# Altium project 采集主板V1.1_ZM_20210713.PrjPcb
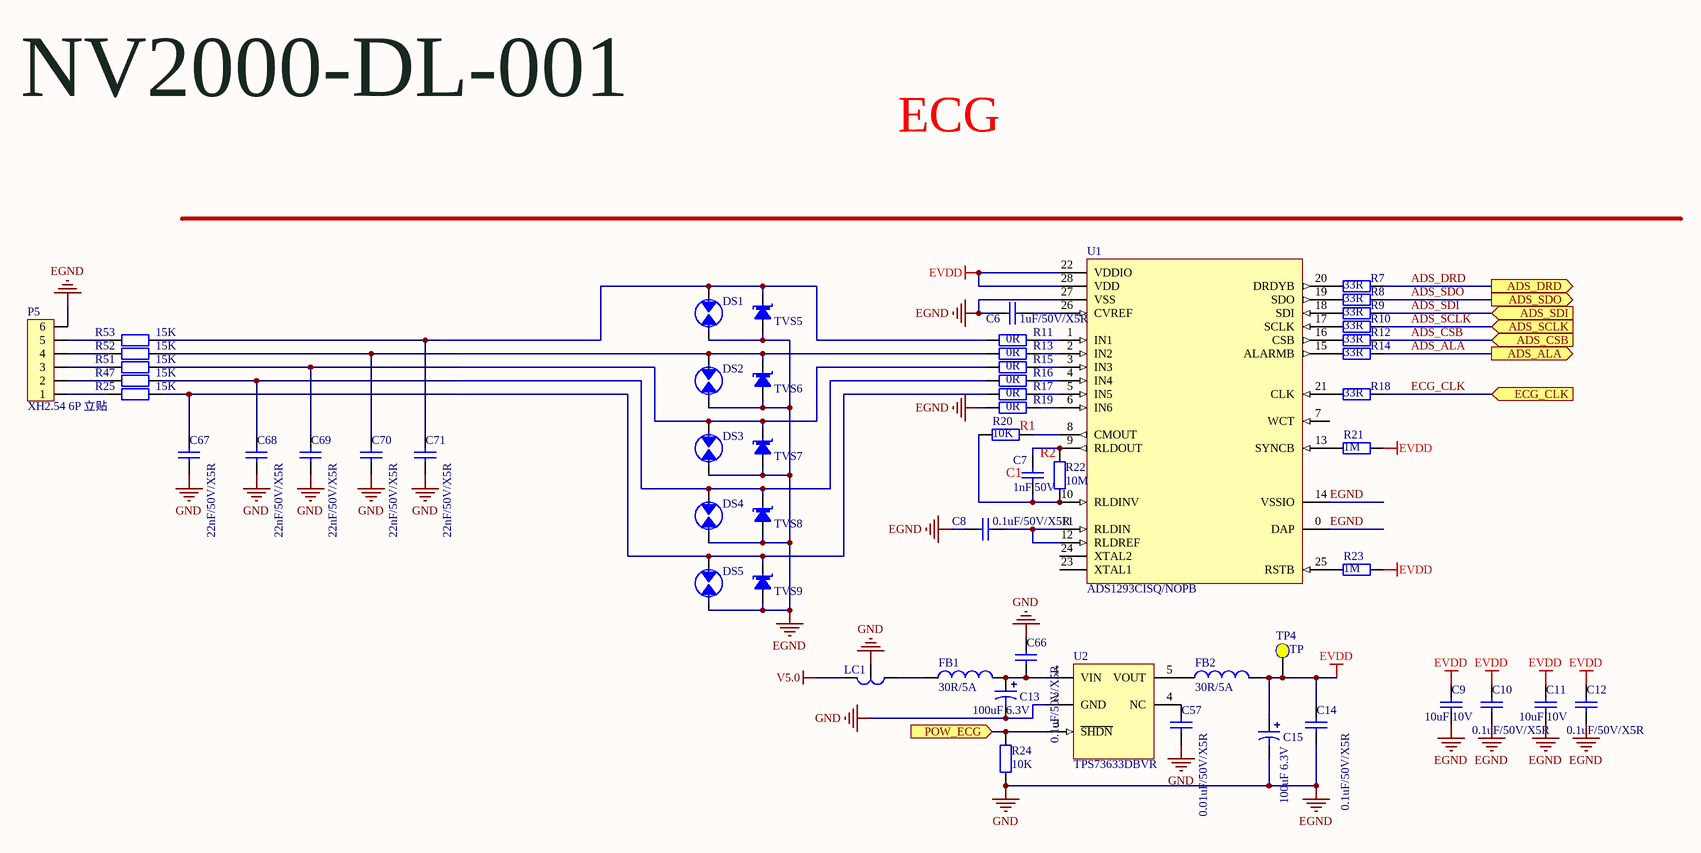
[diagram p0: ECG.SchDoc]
4 sheets, 191 parts. Net scope: flat (ports and power ports of the same name join across sheets).
Board file: 采集主板V1.1_ZM_20210713.PcbDoc
Sheets:
  ECG.SchDoc
  POWER.SchDoc
  PRESS.SchDoc
  控制部分.SchDoc

## Sheet ECG.SchDoc
size A3

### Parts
C6  1uF/50V/X5R  [SMD-0603C]
C7  1nF 50V  [SMD-0603C]
C8  0.1uF/50V/X5R  [SMD-0603C]
C9  10uF 10V  [SMD-0603C]
C10  0.1uF/50V/X5R  [SMD-0603C]
C11  10uF 10V  [SMD-0603C]
C12  0.1uF/50V/X5R  [SMD-0603C]
C13  100uF 6.3V  [SMD-3528-B]
C14  0.1uF/50V/X5R  [SMD-0603C]
C15  100uF 6.3V  [SMD-3528-B]
C57  0.01uF/50V/X5R  [SMD-0603C]
C66  0.1uF/50V/X5R  [SMD-0603C]
C67  22nF/50V/X5R  [SMD-0603C]
C68  22nF/50V/X5R  [SMD-0603C]
C69  22nF/50V/X5R  [SMD-0603C]
C70  22nF/50V/X5R  [SMD-0603C]
C71  22nF/50V/X5R  [SMD-0603C]
DS1  UN1812-90CSMD  [SMD-1812]  (value not drawn)
DS2  UN1812-90CSMD  [SMD-1812]  (value not drawn)
DS3  UN1812-90CSMD  [SMD-1812]  (value not drawn)
DS4  UN1812-90CSMD  [SMD-1812]  (value not drawn)
DS5  UN1812-90CSMD  [SMD-1812]  (value not drawn)
FB1  30R/5A  [0603r]
FB2  30R/5A  [0603r]
LC1  NFM18PC104R1C3  [NFM21P-0805]  (value not drawn)
P5  XH2.54 6P 立贴  [XH-2.54-6P-LI]
R7  33R  [SMD-0603]
R8  33R  [SMD-0603]
R9  33R  [SMD-0603]
R10  33R  [SMD-0603]
R11  0R  [SMD-0805]
R12  33R  [SMD-0603]
R13  0R  [SMD-0805]
R14  33R  [SMD-0603]
R15  0R  [SMD-0805]
R16  0R  [SMD-0805]
R17  0R  [SMD-0805]
R18  33R  [SMD-0603]
R19  0R  [SMD-0805]
R20  10K  [SMD-0603]
R21  1M  [SMD-0603]
R22  10M  [SMD-0603]
R23  1M  [SMD-0603]
R24  10K  [SMD-0603]
R25  15K  [SMD-0603]
R47  15K  [SMD-0603]
R51  15K  [SMD-0603]
R52  15K  [SMD-0603]
R53  15K  [SMD-0603]
TP4  TP  [TP]
TVS5  TVS-S  [SOD-323]  (value not drawn)
TVS6  TVS-S  [SOD-323]  (value not drawn)
TVS7  TVS-S  [SOD-323]  (value not drawn)
TVS8  TVS-S  [SOD-323]  (value not drawn)
TVS9  TVS-S  [SOD-323]  (value not drawn)
U1  ADS1293CISQ/NOPB  [QFN-28]
U2  TPS73633DBVR  [SOT23-5]

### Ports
ADS_ALA (out), ADS_CSB (in), ADS_DRD (out), ADS_SCLK (in), ADS_SDI (in), ADS_SDO (out), ECG_CLK (in), POW_ECG (in)

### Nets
EGND: C6.1 C8.1 C9.1 C10.1 C11.1 C12.1 C13.2 C14.1 C15.2 C57.1 C66.2 C67.1 C68.1 C69.1 C70.1 C71.1 DS1.2 DS2.2 DS3.2 DS4.2 DS5.2 LC1.2 P5.6 R19.1 R24.2 TVS5.1(A) TVS6.1(A) TVS7.1(A) TVS8.1(A) TVS9.1(A) U1.0(DAP) U1.14(VSSIO) U1.27(VSS) U2.2(GND)  [also labelled GND]
EVDD: C9.2 C10.2 C11.2 C12.2 C14.2 C15.1 FB2.2 R21.1 R23.1 TP4.1(TP) U1.22(VDDIO) U1.28(VDD)
V5.0: LC1.3
ADS_ALA: R14.1 ; port ADS_ALA
ADS_CSB: R12.1 ; port ADS_CSB
ADS_DRD: R7.1 ; port ADS_DRD
ADS_SCLK: R10.1 ; port ADS_SCLK
ADS_SDI: R9.1 ; port ADS_SDI
ADS_SDO: R8.1 ; port ADS_SDO
ECG_CLK: R18.1 ; port ECG_CLK
NetC6_2: C6.2 U1.26(CVREF)
NetC7_1: C7.1 R22.1 U1.9(RLDOUT)
NetC7_2: C7.2 R20.2 R22.2 U1.10(RLDINV)
NetC8_2: C8.2 U1.11(RLDIN) U1.12(RLDREF)
NetC13_1: C13.1 C66.1 FB1.2 U2.1(VIN)
NetC57_2: C57.2 U2.4(NC)
NetC67_2: C67.2 DS5.1 R17.1 R25.2 TVS9.2(B)
NetC68_2: C68.2 DS4.1 R16.1 R47.2 TVS8.2(B)
NetC69_2: C69.2 DS3.1 R15.1 R51.2 TVS7.2(B)
NetC70_2: C70.2 DS2.1 R13.1 R52.2 TVS6.2(B)
NetC71_2: C71.2 DS1.1 R11.1 R53.2 TVS5.2(B)
NetFB1_1: FB1.1 LC1.1
NetFB2_1: FB2.1 U2.5(VOUT)
NetP5_1: P5.1 R25.1
NetP5_2: P5.2 R47.1
NetP5_3: P5.3 R51.1
NetP5_4: P5.4 R52.1
NetP5_5: P5.5 R53.1
NetR7_2: R7.2 U1.20(DRDYB)
NetR8_2: R8.2 U1.19(SDO)
NetR9_2: R9.2 U1.18(SDI)
NetR10_2: R10.2 U1.17(SCLK)
NetR11_2: R11.2 U1.1(IN1)
NetR12_2: R12.2 U1.16(CSB)
NetR13_2: R13.2 U1.2(IN2)
NetR14_2: R14.2 U1.15(ALARMB)
NetR15_2: R15.2 U1.3(IN3)
NetR16_2: R16.2 U1.4(IN4)
NetR17_2: R17.2 U1.5(IN5)
NetR18_2: R18.2 U1.21(CLK)
NetR19_2: R19.2 U1.6(IN6)
NetR20_1: R20.1 U1.8(CMOUT)
NetR21_2: R21.2 U1.13(SYNCB)
NetR23_2: R23.2 U1.25(RSTB)
NetR24_1: R24.1 U2.3(~{SHDN}) ; port POW_ECG

Not connected (* = marked no-connect by the designer): U1 7(WCT) 23(XTAL1) 24(XTAL2)

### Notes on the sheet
- NV2000-DL-001
- ECG
- (near R20) R1
- R2
- (near C7) C1

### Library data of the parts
C6 C8 C10 C12 C14 C57 C66-C71 = CAP4: 贴片电容 10%
C7 = CAP4: 贴片电容 5%
C9 C11 = CAP4: 贴片电容 20%
C13 C15 = CAP2: 钽电容
DS1-DS5 = DISCHARE-1: 气体放电管 90V
FB1 FB2 = Inductor: Code_IEC: 1005; Value: 10mH
LC1 = SMD-EMIFIL-0603: LC滤波器
P5 = SIP-6: 心电接口
R7-R19 R21 R23 = RES0: 贴片电阻 5%
R20 R22 R24 R25 R47 R51-R53 = RES0: 贴片电阻 1%
TP4 = TP_POINT
TVS5-TVS9 = TVS-S: 单向TVS
U1 = ADS1293: ECG AFE
U2 = MCP1802: LDO

## Sheet POWER.SchDoc
size A4
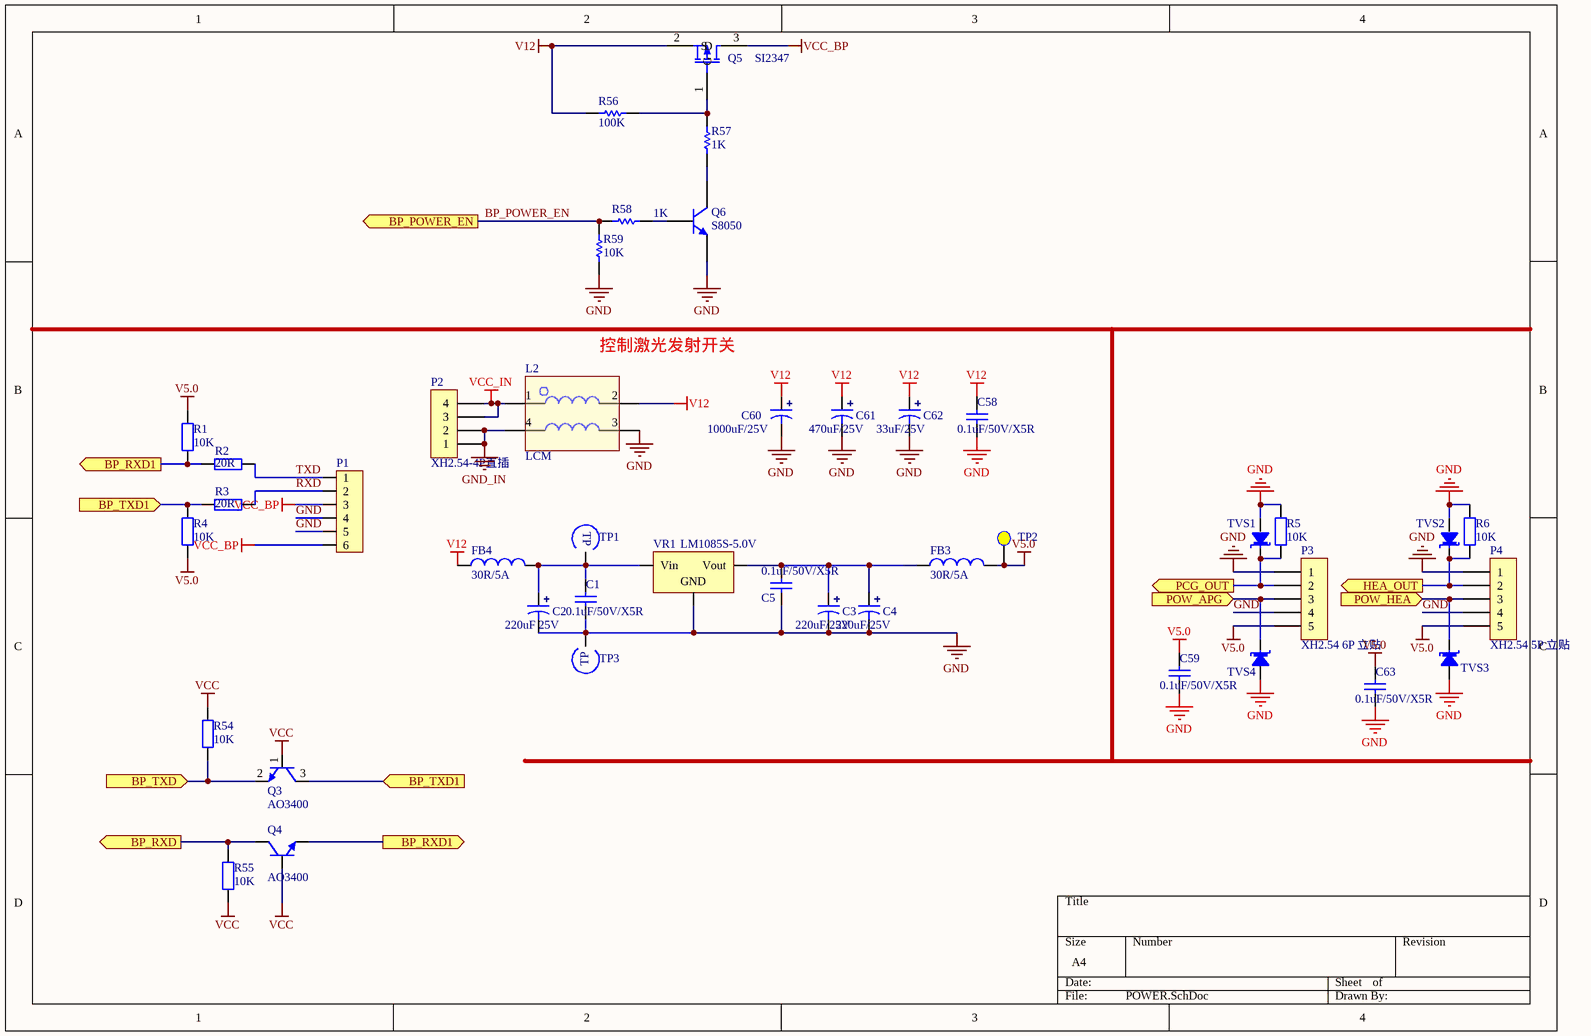
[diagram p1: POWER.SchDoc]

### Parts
C1  0.1uF/50V/X5R  [SMD-0603C]
C2  220uF 25V  [SMD-6.3*7.7]
C3  220uF/25V  [SMD-6.3*7.7]
C4  220uF/25V  [SMD-6.3*7.7]
C5  0.1uF/50V/X5R  [SMD-0603C]
C58  0.1uF/50V/X5R  [SMD-0603C]
C59  0.1uF/50V/X5R  [SMD-0603C]
C60  1000uF/25V  [10*16]
C61  470uF/25V  [8*12]
C62  33uF/25V  [5*7]
C63  0.1uF/50V/X5R  [SMD-0603C]
FB3  30R/5A  [0603r]
FB4  30R/5A  [0603r]
L2  LCM  [LCM]
P1  XH2.54 6P 立贴  [XH-2.54-6P-LI]  (value not drawn)
P2  XH2.54-4P直插  [4X2.54MMZ]
P3  XH2.54 6P 立贴  [XH-2.54-5P-LI]
P4  XH2.54 5P 立贴  [XH-2.54-5P-LI]
Q3  AO3400  [SOT-23]
Q4  AO3400  [SOT-23]
Q5  SI2347  [SOT23-3]
Q6  S8050  [SOT23-3]
R1  10K  [SMD-0603]
R2  20R  [SMD-0603]
R3  20R  [SMD-0603]
R4  10K  [SMD-0603]
R5  10K  [SMD-0603]
R6  10K  [SMD-0603]
R54  10K  [SMD-0603]
R55  10K  [SMD-0603]
R56  100K  [0603R]
R57  1K  [0603R]
R58  1K  [0603R]
R59  10K  [0603R]
TP1  TP  [TP]  (value not drawn)
TP2  TP  [TP]  (value not drawn)
TP3  TP  [TP]  (value not drawn)
TVS1  TVS-S  [SOD-323]  (value not drawn)
TVS2  TVS-S  [SOD-323]  (value not drawn)
TVS3  TVS-S  [SOD-323]  (value not drawn)
TVS4  TVS-S  [SOD-323]  (value not drawn)
VR1  LM1085S-5.0V  [TO-263-3]

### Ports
BP_POWER_EN (out), BP_RXD1 (out), BP_RXD (out), BP_TXD1 (in), BP_TXD (in), HEA_OUT (out), PCG_OUT (out), POW_APG (in), POW_HEA (in)

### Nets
GND: C1.1 C2.2 C3.2 C4.2 C5.1 C58.1 C59.1 C60.2 C61.2 C62.2 C63.1 L2.3 P1.4 P1.5 P3.1 P3.4 P4.1 P4.4 Q6.2(E) R5.1 R6.1 R59.2 TP3.1 TVS1.1(A) TVS2.1(A) TVS3.1(A) TVS4.1(A) VR1.1(GND)  [project net EGND]
GND_IN: L2.4 P2.1 P2.2
V5.0: C59.2 C63.2 FB3.2 P3.5 P4.5 R1.1 R4.2 TP2.1(TP)
V12: C58.2 C60.1 C61.1 C62.1 FB4.1 L2.2 Q5.2(S) R56.2
VCC: Q3.1(B) Q4.1(B) R54.2 R55.1
VCC_BP: P1.3 P1.6 Q5.3(D)
VCC_IN: L2.1 P2.3 P2.4
BP_POWER_EN: R58.2 R59.1 ; port BP_POWER_EN
RXD: P1.2 R3.1
TXD: P1.1 R2.1
NetC1_2: C1.2 C2.1 FB4.2 TP1.1 VR1.3(Vin)
NetC3_1: C3.1 C4.1 C5.2 FB3.1 VR1.2(Vout)
NetP3_2: P3.2 R5.2 TVS1.2(B) ; port PCG_OUT
NetP3_3: P3.3 TVS4.2(B) ; port POW_APG
NetP4_2: P4.2 R6.2 TVS2.2(B) ; port HEA_OUT
NetP4_3: P4.3 TVS3.2(B) ; port POW_HEA
NetQ3_2: Q3.2(E) R54.1 ; port BP_TXD
NetQ3_3: Q3.3(C) R3.2 R4.1 ; port BP_TXD1
NetQ4_2: Q4.2(E) R1.2 R2.2 ; port BP_RXD1
NetQ4_3: Q4.3(C) R55.2 ; port BP_RXD
NetQ5_1: Q5.1(G) R56.1 R57.2
NetQ6_1: Q6.1(B) R58.1
NetQ6_3: Q6.3(C) R57.1

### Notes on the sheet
- (near L2) 控制激光发射开关

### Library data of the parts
C1 C5 C58 C59 C63 = CAP4: 贴片电容 20%
C2-C4 C60-C62 = CAP2: 电解电容
FB3 FB4 = Inductor: Code_IEC: 1005; Value: 10mH
P1 = SIP-6: 血压计接口
P2 = SIP-4
P3 = SIP-5: 颈动脉传感器接口
P4 = SIP-5: 心音传感器接口
Q3 Q4 = NPN-1: NPN
Q5 = MOSFET-P: P-Channel MOSFET
Q6 = NPN: NPN Bipolar Transistor
R1-R6 R54 R55 = R: 贴片电阻 1%
R56-R59 = Res1: Resistor
TP1 TP3 = TP-1: 测试点
TP2 = TP_POINT: 测试点
TVS1-TVS4 = TVS-S: 单向TVS
VR1 = LM1117: 三端稳压器

## Sheet PRESS.SchDoc
size A4
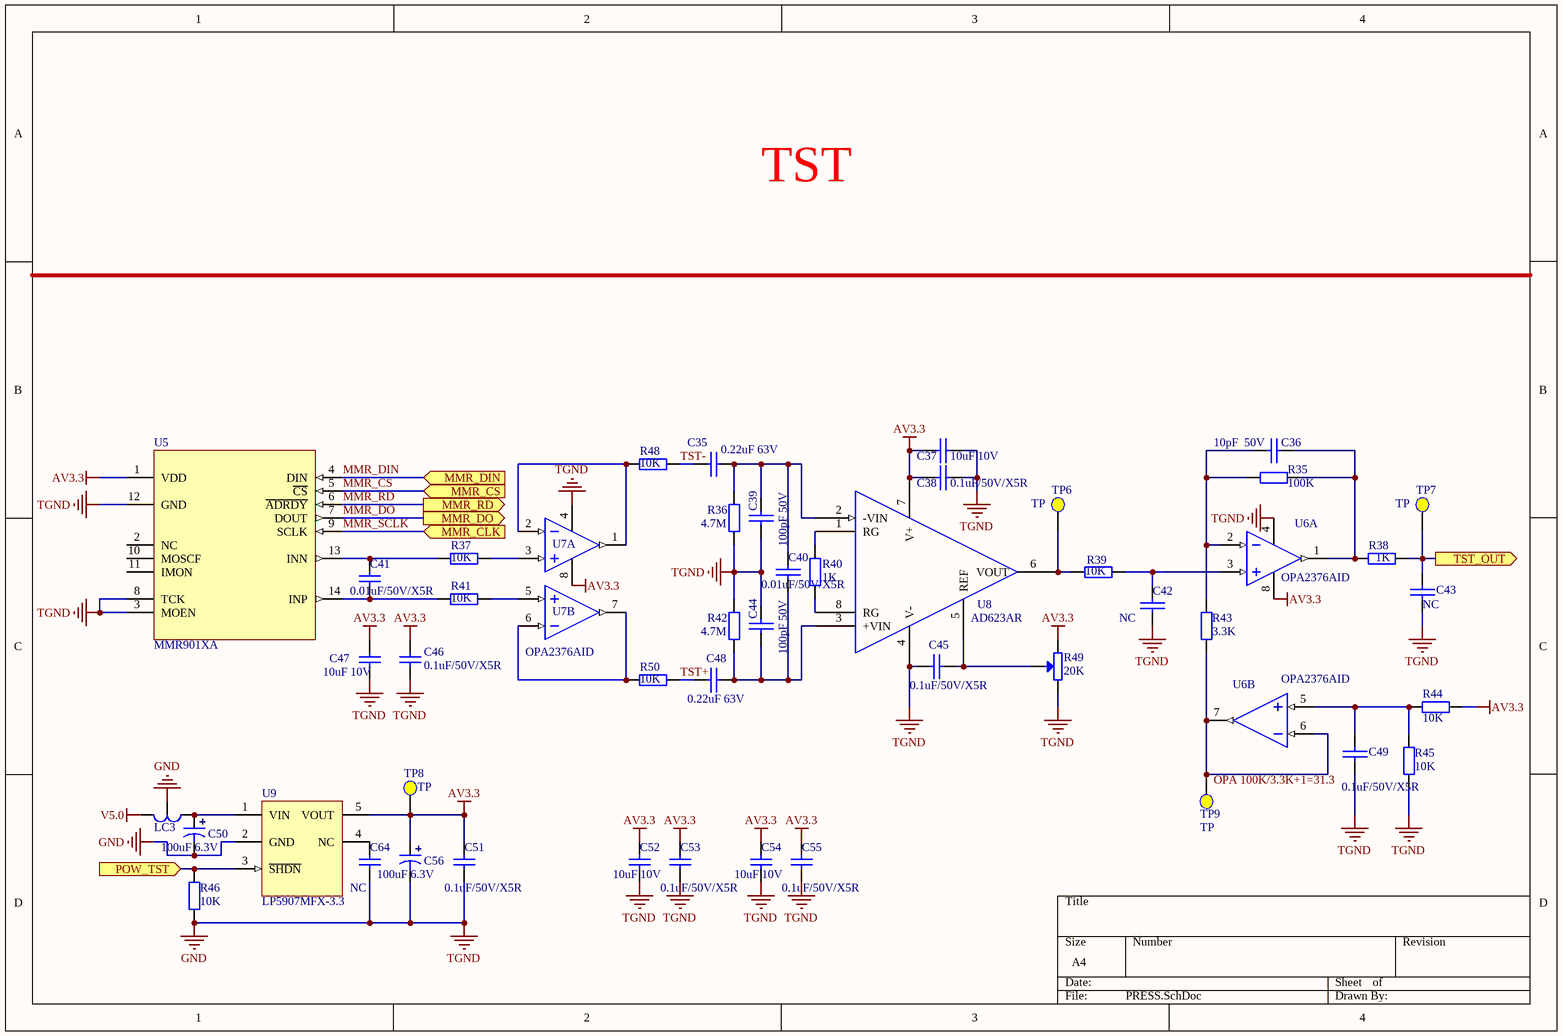
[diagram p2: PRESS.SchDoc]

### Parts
C35  0.22uF 63V  [CAP-7.5*5.08]
C36  10pF  50V  [SMD-0603C]
C37  10uF 10V  [SMD-0603C]
C38  0.1uF/50V/X5R  [SMD-0603C]
C39  100pF 50V  [SMD-0603C]
C40  0.01uF/50V/X5R  [SMD-0603C]
C41  0.01uF/50V/X5R  [SMD-0603C]
C42  NC  [SMD-0603C]
C43  NC  [SMD-0603C]
C44  100pF 50V  [SMD-0603C]
C45  0.1uF/50V/X5R  [SMD-0603C]
C46  0.1uF/50V/X5R  [SMD-0603C]
C47  10uF 10V  [SMD-0603C]
C48  0.22uF 63V  [CAP-7.5*5.08]
C49  0.1uF/50V/X5R  [SMD-0603C]
C50  100uF 6.3V  [SMD-3528-B]
C51  0.1uF/50V/X5R  [SMD-0603C]
C52  10uF 10V  [SMD-0603C]
C53  0.1uF/50V/X5R  [SMD-0603C]
C54  10uF 10V  [SMD-0603C]
C55  0.1uF/50V/X5R  [SMD-0603C]
C56  100uF 6.3V  [SMD-3528-B]
C64  NC  [SMD-0603C]
LC3  NFM18PC104R1C3  [NFM21P-0805]  (value not drawn)
R35  100K  [SMD-0603]
R36  4.7M  [SMD-0603]
R37  10K  [SMD-0603]
R38  1K  [SMD-0603]
R39  10K  [SMD-0603]
R40  1K  [SMD-0603]
R41  10K  [SMD-0603]
R42  4.7M  [SMD-0603]
R43  3.3K  [SMD-0603]
R44  10K  [SMD-0603]
R45  10K  [SMD-0603]
R46  10K  [SMD-0603]
R48  10K  [SMD-0603]
R49  20K  [VR-05]
R50  10K  [SMD-0603]
TP6  TP  [TP]
TP7  TP  [TP]
TP8  TP  [TP]
TP9  TP  [TP]
U5  MMR901XA  [MMR901XA]
U6  OPA2376AID  [SOIC-8]  (parts A,B of 2)
U7  OPA2376AID  [SOIC-8]  (parts A,B of 2)
U8  AD623AR  [SOIC-8]
U9  LP5907MFX-3.3  [SOT23-5]

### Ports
MMR_CLK (in), MMR_CS (in), MMR_DIN (in), MMR_DO (out), MMR_RD (out), POW_TST (in), TST_OUT (out)

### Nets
AV3.3: C37.2 C38.2 C46.2 C47.2 C51.2 C52.2 C53.2 C54.2 C55.2 C56.1 R44.1 R49.3 TP8.1(TP) U5.1(VDD) U6.8(V+) U7.8(V+) U8.7(V+) U9.5(VOUT)
GND: C37.1 C38.1 C39.2 C42.1 C43.2 C44.1 C45.1 C46.1 C47.1 C49.1 C50.2 C51.1 C52.1 C53.1 C54.1 C55.1 C56.2 C64.1 LC3.2 R36.2 R42.1 R45.1 R46.2 R49.1 U5.3(MOEN) U5.8(TCK) U5.12(GND) U6.4(V-) U7.4(V-) U8.4(V-) U9.2(GND)  [also labelled TGND]  [project net EGND]
V5.0: LC3.3
MMR_CS: U5.5(~{CS}) ; port MMR_CS
MMR_DIN: U5.4(DIN) ; port MMR_DIN
MMR_DO: U5.7(DOUT) ; port MMR_DO
MMR_RD: U5.6(~{ADRDY}) ; port MMR_RD
MMR_SCLK: U5.9(SCLK) ; port MMR_CLK
TST+: C48.2 R50.1
TST-: C35.1 R48.1
NetC35_2: C35.2 C39.1 C40.1 R36.1 U8.2(-VIN)
NetC36_1: C36.1 R35.1 R43.2 U6.2(IN1-)
NetC36_2: C36.2 R35.2 R38.1 U6.1(OUT1)
NetC40_2: C40.2 C44.2 C48.1 R42.2 U8.3(+VIN)
NetC41_1: C41.1 R41.2 U5.14(INP)
NetC41_2: C41.2 R37.2 U5.13(INN)
NetC42_2: C42.2 R39.2 U6.3(IN1+)
NetC43_1: C43.1 R38.2 TP7.1(TP) ; port TST_OUT
NetC45_2: C45.2 R49.2 U8.5(REF)
NetC49_2: C49.2 R44.2 R45.2 U6.5(IN2+)
NetC50_1: C50.1 LC3.1 U9.1(VIN)
NetC64_2: C64.2 U9.4(NC)
NetR37_1: R37.1 U7.3(IN1+)
NetR39_1: R39.1 TP6.1(TP) U8.6(VOUT)
NetR40_1: R40.1 U8.1(RG)
NetR40_2: R40.2 U8.8(RG)
NetR41_1: R41.1 U7.5(IN2+)
NetR43_1: R43.1 TP9.1(TP) U6.6(IN2-) U6.7(OUT2)
NetR46_1: R46.1 U9.3(~{SHDN}) ; port POW_TST
NetR48_2: R48.2 U7.1(OUT1) U7.2(IN1-)
NetR50_2: R50.2 U7.6(IN2-) U7.7(OUT2)

Not connected (* = marked no-connect by the designer): U5 2(NC) 10(MOSCF) 11(IMON)

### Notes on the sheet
- TST
- OPA 100K/3.3K+1=31.3

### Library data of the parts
C35 C48 = CAP: CBB电容
C36 C38-C40 C42-C45 C49 = CAP: 贴片电容 5%
C37 = CAP: 贴片电容 20%
C41 C46 C51 C53 C55 C64 = CAP4: 贴片电容 10%
C47 C52 C54 = CAP4: 贴片电容 20%
C50 C56 = CAP2: 钽电容
LC3 = SMD-EMIFIL-0603: LC滤波器
R35-R43 R46 R48 R50 = RES0: 贴片电阻 1%
R44 R45 = RES0: 贴片电阻 1% 低温票电阻
R49 = RES4: 可调电阻
TP6-TP9 = TP_POINT
U5 = MMR901: 压力传感器
U6 = LM358: 运放
U7 = LM358: 高精度运放
U8 = Component_1: 仪表运放; Part Field 1: 0
U9 = MCP1802: LDO

## Sheet 控制部分.SchDoc
size A4
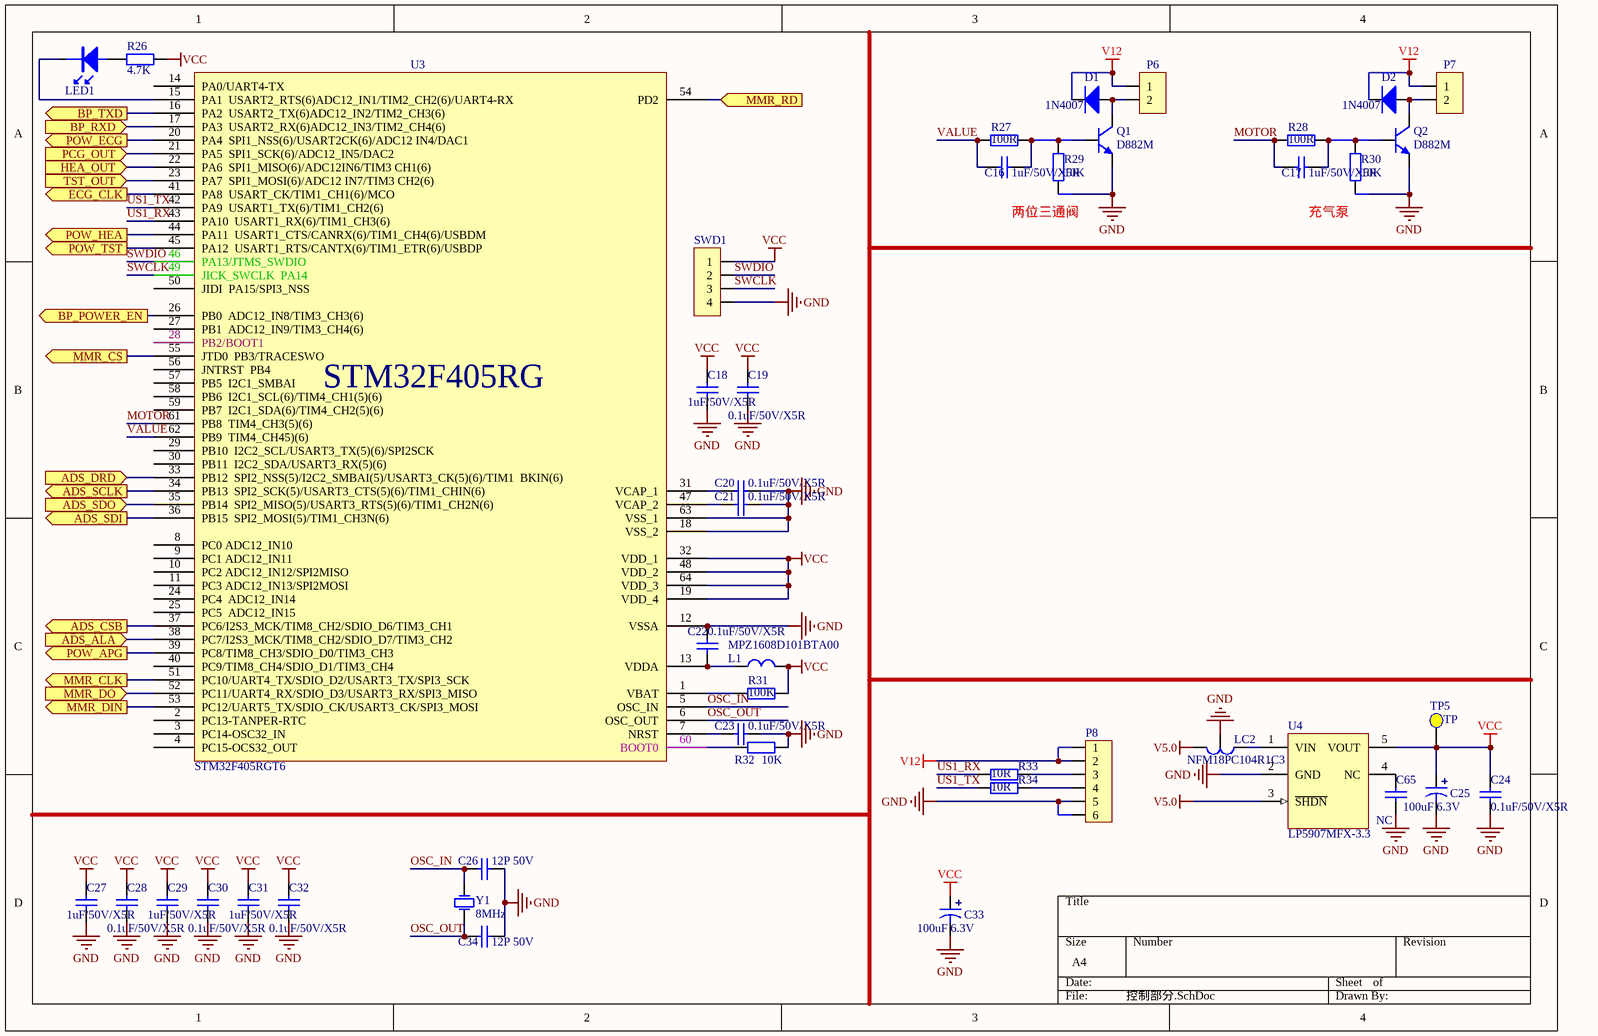
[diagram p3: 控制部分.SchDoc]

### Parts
C16  1uF/50V/X5R  [SMD-0603C]
C17  1uF/50V/X5R  [SMD-0603C]
C18  1uF/50V/X5R  [SMD-0603C]
C19  0.1uF/50V/X5R  [SMD-0603C]
C20  0.1uF/50V/X5R  [SMD-0603C]
C21  0.1uF/50V/X5R  [SMD-0603C]
C22  0.1uF/50V/X5R  [SMD-0603C]
C23  0.1uF/50V/X5R  [SMD-0603C]
C24  0.1uF/50V/X5R  [SMD-0603C]
C25  100uF 6.3V  [SMD-3528-B]
C26  12P 50V  [SMD-0603C]
C27  1uF/50V/X5R  [SMD-0603C]
C28  0.1uF/50V/X5R  [SMD-0603C]
C29  1uF/50V/X5R  [SMD-0603C]
C30  0.1uF/50V/X5R  [SMD-0603C]
C31  1uF/50V/X5R  [SMD-0603C]
C32  0.1uF/50V/X5R  [SMD-0603C]
C33  100uF 6.3V  [SMD-3528-B]
C34  12P 50V  [SMD-0603C]
C65  NC  [SMD-0603C]
D1  1N4007  [DO-214-AC]
D2  1N4007  [DO-214-AC]
L1  MPZ1608D101BTA00  [SMD-0603]
LC2  NFM18PC104R1C3  [NFM18P-0603]
LED1  蓝  [SMD-0603D]  (value not drawn)
P6  VH2.54-2P  [XH-2.54-2P-LI]  (value not drawn)
P7  VH2.54-2P  [XH-2.54-2P-LI]  (value not drawn)
P8  XH2.54 6P 立贴  [XH-2.54-6P-LI]  (value not drawn)
Q1  D882M  [SOT-89-3]
Q2  D882M  [SOT-89-3]
R26  4.7K  [SMD-0603]
R27  100R  [SMD-0603]
R28  100R  [SMD-0603]
R29  10K  [SMD-0603]
R30  10K  [SMD-0603]
R31  100K  [SMD-0603]
R32  10K  [SMD-0603]
R33  10R  [SMD-0603]
R34  10R  [SMD-0603]
SWD1  SIP-4  [SIP-4]  (value not drawn)
TP5  TP  [TP]
U3  STM32F405RGT6  [LQFP64_N]
U4  LP5907MFX-3.3  [SOT23-5]
Y1  8MHz  [XTAL-3225-2]

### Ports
ADS_ALA (in), ADS_CSB (out), ADS_DRD (in), ADS_SCLK (out), ADS_SDI (out), ADS_SDO (in), BP_POWER_EN (out), BP_RXD (in), BP_TXD (out), ECG_CLK (out), HEA_OUT (in), MMR_CLK (out), MMR_CS (out), MMR_DIN (out), MMR_DO (in), MMR_RD (in), PCG_OUT (in), POW_APG (out), POW_ECG (out), POW_HEA (out), POW_TST (out), TST_OUT (in)

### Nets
GND: C18.1 C19.1 C20.1 C21.1 C22.1 C23.2 C24.1 C25.2 C26.1 C27.1 C28.1 C29.1 C30.1 C31.1 C32.1 C33.2 C34.1 C65.1 LC2.2 P8.5 P8.6 Q1.3(E) Q2.3(E) R29.2 R30.2 R32.2 SWD1.4 U3.12(VSSA) U3.18(VSS_2) U3.63(VSS_1) U4.2(GND)  [project net EGND]
V5.0: LC2.3 U4.3(~{SHDN})
V12: D1.2(K) D2.2(K) P6.1 P7.1 P8.1 P8.2
VCC: C18.2 C19.2 C24.2 C25.1 C27.2 C28.2 C29.2 C30.2 C31.2 C32.2 C33.1 L1.2 R26.1 R31.1 SWD1.1 TP5.1(TP) U3.19(VDD_4) U3.32(VDD_1) U3.48(VDD_2) U3.64(VDD_3) U4.5(VOUT)
ADS_ALA: U3.38(PC7/I2S3_MCK/TIM8_CH2/SDIO_D7/TIM3_CH2) ; port ADS_ALA
ADS_CSB: U3.37(PC6/I2S3_MCK/TIM8_CH2/SDIO_D6/TIM3_CH1) ; port ADS_CSB
ADS_DRD: U3.33(PB12__SPI2_NSS(5)/I2C2_SMBAI(5)/USART3_CK(5)(6)/TIM1__BKIN(6)) ; port ADS_DRD
ADS_SCLK: U3.34(PB13__SPI2_SCK(5)/USART3_CTS(5)(6)/TIM1_CHIN(6)) ; port ADS_SCLK
ADS_SDI: U3.36(PB15__SPI2_MOSI(5)/TIM1_CH3N(6)) ; port ADS_SDI
ADS_SDO: U3.35(PB14__SPI2_MISO(5)/USART3_RTS(5)(6)/TIM1_CH2N(6)) ; port ADS_SDO
BP_POWER_EN: U3.26(PB0__ADC12_IN8/TIM3_CH3(6)) ; port BP_POWER_EN
ECG_CLK: U3.41(PA8__USART_CK/TIM1_CH1(6)/MCO) ; port ECG_CLK
MMR_CS: U3.55(JTD0__PB3/TRACESWO) ; port MMR_CS
MMR_DIN: U3.53(PC12/UART5_TX/SDIO_CK/USART3_CK/SPI3_MOSI) ; port MMR_DIN
MMR_DO: U3.52(PC11/UART4_RX/SDIO_D3/USART3_RX/SPI3_MISO) ; port MMR_DO
MMR_RD: U3.54(PD2) ; port MMR_RD
MMR_SCLK: U3.51(PC10/UART4_TX/SDIO_D2/USART3_TX/SPI3_SCK) ; port MMR_CLK
MOTOR: C17.2 R28.2 U3.61(PB8__TIM4_CH3(5)(6))
OSC_IN: C26.2 U3.5(OSC_IN) Y1.2(OSC2)
OSC_OUT: C34.2 U3.6(OSC_OUT) Y1.1(OSC1)
SWCLK: SWD1.3 U3.49(JICK_SWCLK__PA14)
SWDIO: SWD1.2 U3.46(PA13/JTMS_SWDIO)
US1_RX: R33.2 U3.43(PA10__USART1_RX(6)/TIM1_CH3(6))
US1_TX: R34.2 U3.42(PA9__USART1_TX(6)/TIM1_CH2(6))
VALUE: C16.2 R27.2 U3.62(PB9__TIM4_CH45)(6))
NetC16_1: C16.1 Q1.1(B) R27.1 R29.1
NetC17_1: C17.1 Q2.1(B) R28.1 R30.1
NetC20_2: C20.2 U3.31(VCAP_1)
NetC21_2: C21.2 U3.47(VCAP_2)
NetC22_2: C22.2 L1.1 U3.13(VDDA)
NetC23_1: C23.1 U3.7(NRST)
NetC43_1: U3.23(PA7__SPI1_MOSI(6)/ADC12_IN7/TIM3_CH2(6)) ; port TST_OUT
NetC65_2: C65.2 U4.4(NC)
NetD1_1: D1.1(A) P6.2 Q1.2(C)
NetD2_1: D2.1(A) P7.2 Q2.2(C)
NetLC2_1: LC2.1 U4.1(VIN)
NetLED1_1: LED1.1 R26.2
NetLED1_2: LED1.2 U3.15(PA1__USART2_RTS(6)ADC12_IN1/TIM2_CH2(6)/UART4-RX)
NetP3_2: U3.21(PA5__SPI1_SCK(6)/ADC12_IN5/DAC2) ; port PCG_OUT
NetP3_3: U3.39(PC8/TIM8_CH3/SDIO_D0/TIM3_CH3) ; port POW_APG
NetP4_2: U3.22(PA6__SPI1_MISO(6)/ADC12IN6/TIM3_CH1(6)) ; port HEA_OUT
NetP4_3: U3.44(PA11__USART1_CTS/CANRX(6)/TIM1_CH4(6)/USBDM) ; port POW_HEA
NetP8_3: P8.3 R33.1
NetP8_4: P8.4 R34.1
NetQ3_2: U3.16(PA2__USART2_TX(6)ADC12_IN2/TIM2_CH3(6)) ; port BP_TXD
NetQ4_3: U3.17(PA3__USART2_RX(6)ADC12_IN3/TIM2_CH4(6)) ; port BP_RXD
NetR24_1: U3.20(PA4__SPI1_NSS(6)/USART2CK(6)/ADC12_IN4/DAC1) ; port POW_ECG
NetR31_2: R31.2 U3.1(VBAT)
NetR32_1: R32.1 U3.60(BOOT0)
NetR46_1: U3.45(PA12__USART1_RTS/CANTX(6)/TIM1_ETR(6)/USBDP) ; port POW_TST

Not connected (* = marked no-connect by the designer): U3 2(PC13-TANPER-RTC) 3(PC14-OSC32_IN) 4(PC15-OCS32_OUT) 8(PC0_ADC12_IN10) 9(PC1_ADC12_IN11) 10(PC2_ADC12_IN12/SPI2MISO) 11(PC3_ADC12_IN13/SPI2MOSI) 14(PA0/UART4-TX) 24(PC4__ADC12_IN14) 25(PC5__ADC12_IN15) 27(PB1__ADC12_IN9/TIM3_CH4(6)) 28(PB2/BOOT1) 29(PB10__I2C2_SCL/USART3_TX(5)(6)/SPI2SCK) 30(PB11__I2C2_SDA/USART3_RX(5)(6)) 40(PC9/TIM8_CH4/SDIO_D1/TIM3_CH4) 50(JIDI__PA15/SPI3_NSS) 56(JNTRST__PB4) 57(PB5__I2C1_SMBAI) 58(PB6__I2C1_SCL(6)/TIM4_CH1(5)(6)) 59(PB7__I2C1_SDA(6)/TIM4_CH2(5)(6))

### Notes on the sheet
- 两位三通阀
- 充气泵

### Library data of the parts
C16-C23 C26-C32 C34 = CAP4: 贴片电容 20%
C24 = CAP4: 贴片电容
C25 C33 = CAP2: 钽电容
C65 = CAP4: 贴片电容 10%
D1 D2 = DIODE2: 二极管 M7
L1 = CIZHU1: 磁珠电感 100R 100MHz
LC2 = SMD-EMIFIL-0603: LC滤波器
LED1 = LED0: LED
P6 P7 = SIP-2: 2.54mm- 2P立贴
P8 = SIP-6: 血压计接口
Q1 Q2 = NPN-TO252: NPN TO252
R26 = RES2: 贴片电阻
R27-R30 = RES-SOP: 贴片电阻 5%
R31-R34 = RES2: 贴片电阻 5%
TP5 = TP_POINT
U3 = STM32F405RG: MCU
U4 = MCP1802: LDO
Y1 = XTAL: 晶振

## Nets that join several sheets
EGND: ECG (34 pins), POWER (28 pins), PRESS (31 pins), 控制部分 (31 pins)
V5.0: ECG (LC1.3), POWER (8 pins), PRESS (LC3.3), 控制部分 (LC2.3 U4.3)
V12: POWER (8 pins), 控制部分 (6 pins)
VCC: POWER (Q3.1 Q4.1 R54.2 R55.1), 控制部分 (21 pins)
ADS_ALA: ECG (R14.1), 控制部分 (U3.38)
ADS_CSB: ECG (R12.1), 控制部分 (U3.37)
ADS_DRD: ECG (R7.1), 控制部分 (U3.33)
ADS_SCLK: ECG (R10.1), 控制部分 (U3.34)
ADS_SDI: ECG (R9.1), 控制部分 (U3.36)
ADS_SDO: ECG (R8.1), 控制部分 (U3.35)
BP_POWER_EN: POWER (R58.2 R59.1), 控制部分 (U3.26)
ECG_CLK: ECG (R18.1), 控制部分 (U3.41)
MMR_CS: PRESS (U5.5), 控制部分 (U3.55)
MMR_DIN: PRESS (U5.4), 控制部分 (U3.53)
MMR_DO: PRESS (U5.7), 控制部分 (U3.52)
MMR_RD: PRESS (U5.6), 控制部分 (U3.54)
MMR_SCLK: PRESS (U5.9), 控制部分 (U3.51)
NetC43_1: PRESS (C43.1 R38.2 TP7.1), 控制部分 (U3.23)
NetP3_2: POWER (P3.2 R5.2 TVS1.2), 控制部分 (U3.21)
NetP3_3: POWER (P3.3 TVS4.2), 控制部分 (U3.39)
NetP4_2: POWER (P4.2 R6.2 TVS2.2), 控制部分 (U3.22)
NetP4_3: POWER (P4.3 TVS3.2), 控制部分 (U3.44)
NetQ3_2: POWER (Q3.2 R54.1), 控制部分 (U3.16)
NetQ4_3: POWER (Q4.3 R55.2), 控制部分 (U3.17)
NetR24_1: ECG (R24.1 U2.3), 控制部分 (U3.20)
NetR46_1: PRESS (R46.1 U9.3), 控制部分 (U3.45)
